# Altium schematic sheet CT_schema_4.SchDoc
size 184 x 159 mm
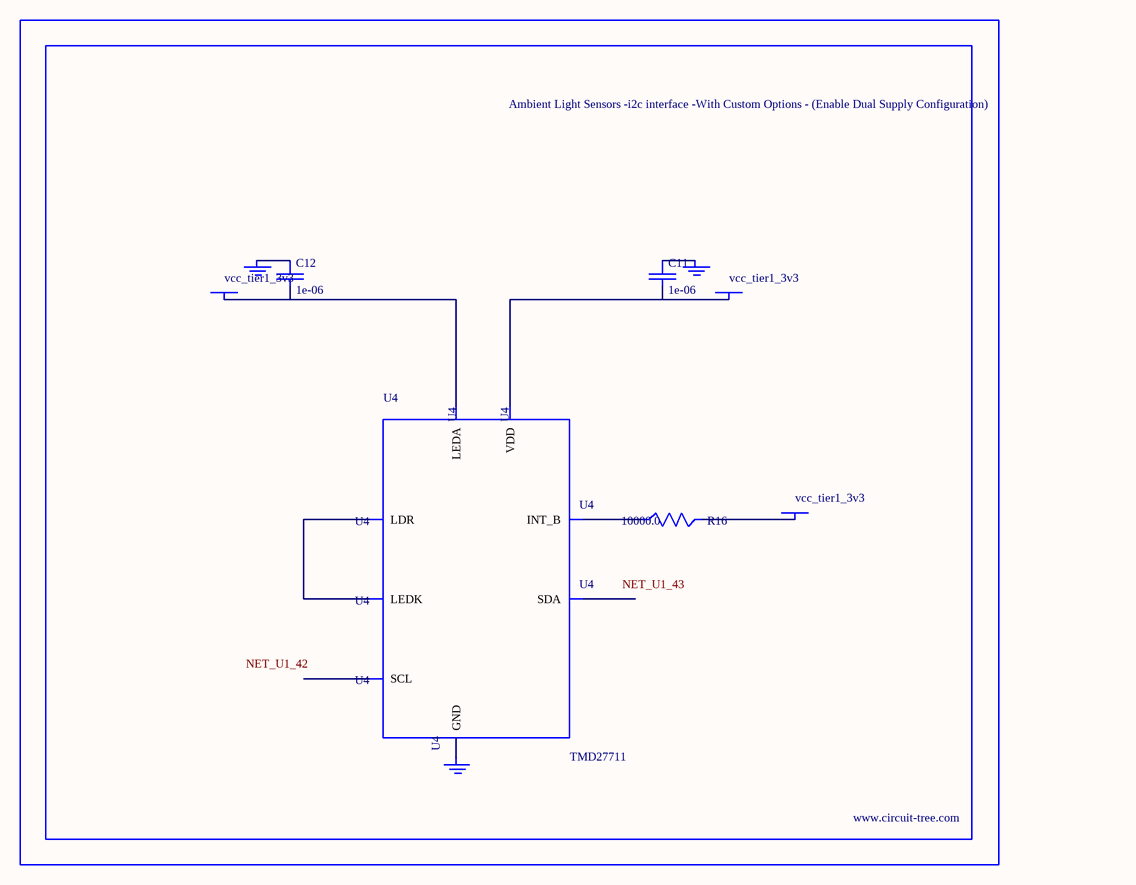
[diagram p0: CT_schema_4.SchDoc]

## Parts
BORDER3  (no value)
C11  1e-06  [C0603]
C12  1e-06  [C0603]
GND_INSTANCE_3_0  (no value)
GND_INSTANCE_3_1  (no value)
GND_INSTANCE_3_2  (no value)
POWER_INSTANCE_3_0  vcc_tier1_3v3
POWER_INSTANCE_3_1  vcc_tier1_3v3
POWER_INSTANCE_3_2  vcc_tier1_3v3
R16  10000.0  [R0603]
U4  TMD27711  [SMD-8]

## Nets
NetC11_1: C11.1 GND_INSTANCE_3_0.0(GND)
NetC11_2: C11.2 POWER_INSTANCE_3_0.0(PWR) U4.1(VDD)
NetC12_1: C12.1 GND_INSTANCE_3_1.0(GND)
NetC12_2: C12.2 POWER_INSTANCE_3_1.0(PWR) U4.4(LEDA)
NetGND_INSTANCE_3_2_0: GND_INSTANCE_3_2.0(GND) U4.3(GND)
NetPOWER_INSTANCE_3_2_0: POWER_INSTANCE_3_2.0(PWR) R16.2
NetR16_1: R16.1 U4.7(INT_B)
NetU4_5: U4.5(LEDK) U4.6(LDR)

Not connected (* = marked no-connect by the designer): U4 2(SCL) 8(SDA)

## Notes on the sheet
- Labels drawn without touching a wire or pin: NET_U1_42, NET_U1_43

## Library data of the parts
BORDER3 = BORDER_PAGE3
C11 C12 = C0603C105K3RACTU
GND_INSTANCE_3_0-GND_INSTANCE_3_2 = GND
POWER_INSTANCE_3_0-POWER_INSTANCE_3_2 = PWR
R16 = RC0603JR-0710KL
